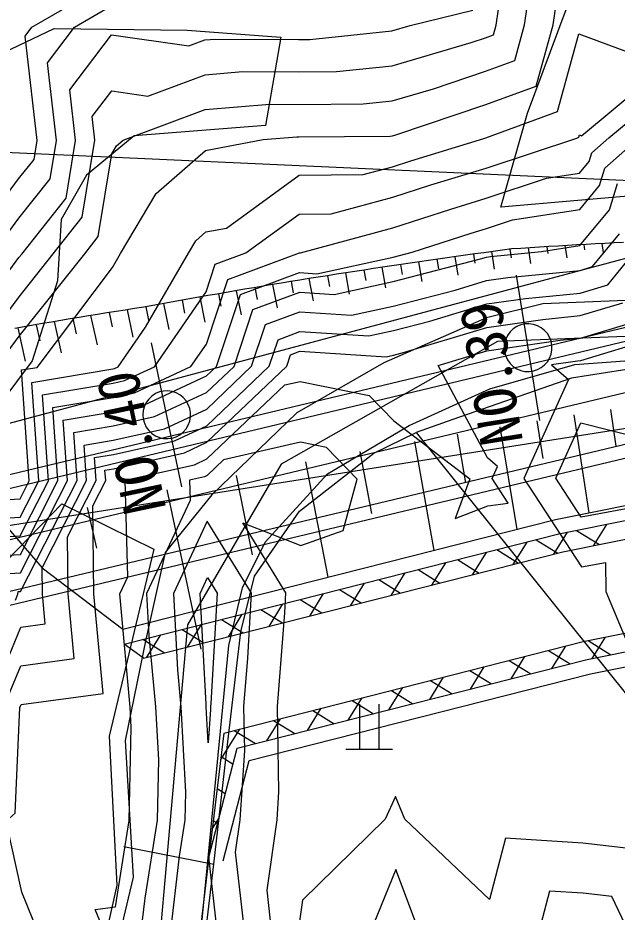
# Model space of a CAD drawing. Extents: x 42655 to 43811, y -141820 to -141156.
# Drawn here: x 43280.88 to 43313.48, y -141374.58 to -141325.97 of the extents above; entities that cross this region are included whole.
import ezdxf

# ---------------------------------------------------------------- set-up
doc = ezdxf.new("R2010")
doc.units = 0
for name, color, linetype in [('D-BMK-HTXT_1', 7, 'Continuous'), ('D-BMK_1', 7, 'Continuous'), ('D-STR', 7, 'Continuous'), ('D-STR-STR4_1', 7, 'Continuous'), ('D-STR-STR5_1', 7, 'Continuous'), ('D-STR_1', 7, 'Continuous'), ('ZE_HICN', 7, 'Continuous'), ('ZE_LWCN', 7, 'Continuous'), ('地形', 7, 'Continuous'), ('現況水路ﾊｯﾁ', 7, 'Continuous')]:
    doc.layers.add(name, color=color, linetype=linetype)

msp = doc.modelspace()

# ---------------------------------------------------------------- linework, layer by layer
at = {"layer": 'D-BMK-HTXT_1'}
for p, q in [((43439.808, -141340.537), (43274.802, -141333.044)), ((43309.27, -141347.849), (43308.009, -141339.949)), ((43289.804, -141351.457), (43288.149, -141343.63))]:
    msp.add_line(p, q, dxfattribs=at)
for points in [[(43307.339, -141343.899), (43307.36, -141344.131), (43307.422, -141344.356), (43307.524, -141344.566), (43307.66, -141344.754), (43307.829, -141344.915), (43308.023, -141345.044), (43308.238, -141345.135), (43308.465, -141345.187), (43308.698, -141345.198), (43308.929, -141345.166), (43309.15, -141345.094), (43309.356, -141344.984), (43309.538, -141344.839), (43309.691, -141344.663), (43309.811, -141344.463), (43309.893, -141344.245), (43309.934, -141344.015), (43309.934, -141343.782), (43309.893, -141343.553), (43309.811, -141343.335), (43309.691, -141343.135), (43309.538, -141342.959), (43309.356, -141342.814), (43309.15, -141342.703), (43308.929, -141342.631), (43308.698, -141342.6), (43308.465, -141342.611), (43308.238, -141342.663), (43308.023, -141342.754), (43307.829, -141342.883), (43307.66, -141343.044), (43307.523, -141343.232), (43307.422, -141343.442), (43307.36, -141343.667), (43307.339, -141343.899)], [(43287.677, -141347.544), (43287.697, -141347.776), (43287.759, -141348.001), (43287.861, -141348.211), (43287.998, -141348.399), (43288.166, -141348.56), (43288.361, -141348.689), (43288.575, -141348.78), (43288.802, -141348.832), (43289.035, -141348.843), (43289.266, -141348.811), (43289.487, -141348.739), (43289.693, -141348.629), (43289.875, -141348.483), (43290.028, -141348.308), (43290.148, -141348.108), (43290.23, -141347.89), (43290.271, -141347.66), (43290.271, -141347.427), (43290.23, -141347.198), (43290.148, -141346.98), (43290.028, -141346.78), (43289.875, -141346.604), (43289.693, -141346.459), (43289.487, -141346.348), (43289.266, -141346.276), (43289.035, -141346.245), (43288.802, -141346.256), (43288.575, -141346.307), (43288.361, -141346.399), (43288.166, -141346.527), (43287.998, -141346.689), (43287.861, -141346.877), (43287.759, -141347.087), (43287.697, -141347.312), (43287.677, -141347.544)]]:
    msp.add_lwpolyline(points, dxfattribs=at)
at = {"layer": 'D-BMK_1'}
msp.add_lwpolyline([(43339.878, -141340.165), (43219.961, -141368.793)], dxfattribs=at)
at = {"layer": 'D-STR'}
for p, q in [((43312.899, -141353.503), (43312.177, -141354.668)), ((43310.766, -141353.932), (43310.026, -141355.127)), ((43311.272, -141353.83), (43312.516, -141354.6)), ((43308.569, -141354.464), (43307.812, -141355.687)), ((43309.074, -141354.336), (43310.257, -141355.068)), ((43306.355, -141355.024), (43305.597, -141356.247)), ((43306.934, -141354.878), (43308.116, -141355.61)), ((43304.794, -141355.419), (43305.976, -141356.152)), ((43302.653, -141355.961), (43303.835, -141356.693)), ((43304.14, -141355.585), (43303.383, -141356.808)), ((43300.513, -141356.502), (43301.695, -141357.235)), ((43301.926, -141356.145), (43301.168, -141357.368)), ((43299.712, -141356.705), (43298.954, -141357.928)), ((43297.497, -141357.265), (43296.74, -141358.489)), ((43298.372, -141357.044), (43299.554, -141357.776)), ((43295.283, -141357.826), (43294.525, -141359.049)), ((43296.232, -141357.586), (43297.414, -141358.318)), ((43293.069, -141358.386), (43292.311, -141359.609)), ((43294.091, -141358.127), (43295.274, -141358.86)), ((43291.951, -141358.669), (43293.133, -141359.401)), ((43289.81, -141359.21), (43290.993, -141359.943)), ((43290.854, -141358.946), (43290.097, -141360.169)), ((43287.67, -141359.752), (43288.852, -141360.484)), ((43288.64, -141359.507), (43287.882, -141360.73)), ((43311.904, -141359.823), (43313.147, -141360.593)), ((43312.835, -141359.636), (43312.113, -141360.801)), ((43287.716, -141360.772), (43286.667, -141360.006)), ((43309.75, -141360.356), (43310.93, -141361.087)), ((43310.666, -141360.124), (43309.909, -141361.346)), ((43308.45, -141360.687), (43307.695, -141361.906)), ((43306.234, -141361.25), (43305.48, -141362.466)), ((43307.612, -141360.9), (43308.789, -141361.629)), ((43304.017, -141361.813), (43303.266, -141363.026)), ((43305.474, -141361.443), (43306.649, -141362.17)), ((43303.336, -141361.986), (43304.508, -141362.712)), ((43301.801, -141362.376), (43301.051, -141363.587)), ((43301.198, -141362.529), (43302.368, -141363.254)), ((43299.585, -141362.939), (43298.837, -141364.147)), ((43299.061, -141363.072), (43300.227, -141363.795)), ((43297.369, -141363.502), (43296.623, -141364.707)), ((43296.923, -141363.616), (43298.087, -141364.337)), ((43295.153, -141364.065), (43294.408, -141365.268)), ((43294.785, -141364.159), (43295.946, -141364.878)), ((43292.937, -141364.629), (43291.911, -141366.284)), ((43292.647, -141364.702), (43293.806, -141365.42)), ((43292.087, -141364.845), (43291.266, -141371.584)), ((43291.266, -141371.584), (43292.808, -141365.672)), ((43291.931, -141366.126), (43292.584, -141366.531)), ((43292.04, -141371.786), (43293.463, -141366.332)), ((43291.719, -141367.862), (43292.165, -141368.138)), ((43291.826, -141369.436), (43291.454, -141370.037)), ((43291.508, -141369.599), (43291.746, -141369.746)), ((43286.641, -141371.017), (43291.547, -141371.981)), ((43291.296, -141371.335), (43291.326, -141371.353))]:
    msp.add_line(p, q, dxfattribs=at)
for points in [[(43286.592, -141359.199), (43310.131, -141353.244), (43329.384, -141349.374), (43339.497, -141347.728), (43344.858, -141358.537)], [(43286.667, -141360.006), (43310.308, -141354.024), (43329.528, -141350.161), (43339.043, -141348.612), (43344.134, -141358.878)], [(43287.716, -141360.772), (43310.53, -141355), (43329.706, -141351.145), (43338.475, -141349.718), (43343.23, -141359.304)], [(43292.087, -141364.845), (43311.636, -141359.877), (43330.601, -141356.065), (43335.636, -141355.246), (43338.236, -141361.658)], [(43292.808, -141365.672), (43311.857, -141360.853), (43330.78, -141357.049), (43335.009, -141356.361), (43337.332, -141362.083)], [(43293.463, -141366.332), (43312.034, -141361.633), (43330.923, -141357.836), (43334.508, -141357.253), (43336.61, -141362.424)]]:
    msp.add_lwpolyline(points, dxfattribs=at)
at = {"layer": 'D-STR-STR4_1'}
for p, q in [((43313.118, -141347.254), (43313.418, -141349.26)), ((43311.123, -141347.558), (43311.947, -141352.879)), ((43307.099, -141348.202), (43308.02, -141353.778)), ((43309.11, -141347.874), (43309.437, -141349.918)), ((43304.777, -141348.593), (43305.23, -141351.238)), ((43302.457, -141348.997), (43303.511, -141354.931)), ((43299.492, -141349.536), (43300.119, -141352.912)), ((43296.532, -141350.096), (43297.746, -141356.377)), ((43292.75, -141350.846), (43293.626, -141355.153)), ((43288.975, -141351.633), (43290.825, -141360.293)), ((43284.651, -141352.582), (43285.148, -141354.789)), ((43280.239, -141353.603), (43282.194, -141355.865)), ((43282.194, -141355.865), (43286.592, -141359.199))]:
    msp.add_line(p, q, dxfattribs=at)
at = {"layer": 'D-STR-STR5_1'}
for p, q in [((43308.788, -141339.32), (43308.655, -141338.475)), ((43309.659, -141338.413), (43309.718, -141338.789)), ((43310.764, -141339.014), (43310.664, -141338.353)), ((43311.668, -141338.295), (43311.71, -141338.58)), ((43312.742, -141338.717), (43312.672, -141338.24)), ((43304.84, -141339.961), (43304.671, -141338.953)), ((43305.664, -141338.815), (43305.745, -141339.306)), ((43306.813, -141339.635), (43306.658, -141338.679)), ((43307.651, -141338.546), (43307.726, -141339.011)), ((43301.692, -141339.381), (43301.788, -141339.924)), ((43302.868, -141340.296), (43302.685, -141339.236)), ((43303.678, -141339.093), (43303.766, -141339.61)), ((43298.93, -141340.996), (43298.717, -141339.832)), ((43299.708, -141339.68), (43299.811, -141340.248)), ((43300.898, -141340.641), (43300.7, -141339.529)), ((43295.744, -141340.305), (43295.862, -141340.926)), ((43296.963, -141341.36), (43296.735, -141340.145)), ((43297.726, -141339.988), (43297.836, -141340.582)), ((43293.036, -141342.118), (43292.774, -141340.801)), ((43293.764, -141340.633), (43293.89, -141341.279)), ((43294.998, -141341.735), (43294.754, -141340.468)), ((43289.808, -141341.318), (43289.951, -141342.015)), ((43291.075, -141342.512), (43290.796, -141341.143)), ((43291.785, -141340.971), (43291.92, -141341.642)), ((43287.159, -141343.329), (43286.839, -141341.834)), ((43287.832, -141341.675), (43287.984, -141342.398)), ((43289.116, -141342.916), (43288.82, -141341.495)), ((43283.862, -141342.316), (43284.045, -141343.141)), ((43285.204, -141343.751), (43284.854, -141342.153)), ((43285.847, -141341.992), (43286.014, -141342.765)), ((43281.301, -141344.626), (43280.887, -141342.82)), ((43281.878, -141342.65), (43282.077, -141343.527)), ((43283.251, -141344.184), (43282.87, -141342.481))]:
    msp.add_line(p, q, dxfattribs=at)
msp.add_lwpolyline([(43313.829, -141338.18), (43313.322, -141338.206), (43312.815, -141338.232), (43312.308, -141338.26), (43311.8, -141338.288), (43311.293, -141338.316), (43310.786, -141338.345), (43310.279, -141338.375), (43309.772, -141338.406), (43309.265, -141338.437), (43308.758, -141338.469), (43308.25, -141338.501), (43307.743, -141338.534), (43307.241, -141338.601), (43306.739, -141338.668), (43306.237, -141338.736), (43305.736, -141338.805), (43305.234, -141338.874), (43304.732, -141338.944), (43304.231, -141339.015), (43303.729, -141339.086), (43303.228, -141339.158), (43302.727, -141339.23), (43302.225, -141339.303), (43301.724, -141339.377), (43301.223, -141339.451), (43300.722, -141339.526), (43300.221, -141339.602), (43299.72, -141339.678), (43299.22, -141339.755), (43298.719, -141339.832), (43298.218, -141339.91), (43297.718, -141339.989), (43297.217, -141340.068), (43296.717, -141340.148), (43296.217, -141340.229), (43295.717, -141340.31), (43295.216, -141340.392), (43294.716, -141340.474), (43294.216, -141340.557), (43293.717, -141340.641), (43293.217, -141340.725), (43292.717, -141340.81), (43292.218, -141340.896), (43291.718, -141340.982), (43291.219, -141341.069), (43290.719, -141341.157), (43290.22, -141341.245), (43289.721, -141341.333), (43289.222, -141341.423), (43288.723, -141341.513), (43288.224, -141341.603), (43287.725, -141341.695), (43287.224, -141341.773), (43286.722, -141341.852), (43286.221, -141341.932), (43285.72, -141342.012), (43285.219, -141342.093), (43284.717, -141342.175), (43284.216, -141342.257), (43283.715, -141342.34), (43283.214, -141342.424), (43282.713, -141342.508), (43282.213, -141342.593), (43281.712, -141342.678), (43281.211, -141342.764), (43280.711, -141342.851)], dxfattribs=at)
at = {"layer": 'D-STR_1'}
for points in [[(43339.6, -141336.676), (43218.633, -141365.555)], [(43339.659, -141337.424), (43218.917, -141366.249)], [(43317.868, -141337.995), (43218.254, -141364.63)], [(43340.097, -141342.907), (43221.004, -141371.338)], [(43340.157, -141343.654), (43221.288, -141372.032)], [(43340.196, -141344.153), (43280.239, -141353.603)]]:
    msp.add_lwpolyline(points, dxfattribs=at)
at = {"layer": 'ZE_HICN'}
for points in [[(43278.608, -141342.146), (43280.936, -141339.002), (43281.089, -141338.809), (43283.504, -141335.764), (43284.022, -141332.633), (43283.709, -141329.882), (43285.967, -141326.888), (43290.184, -141327.5), (43291.057, -141327.174), (43291.628, -141327.127), (43296.145, -141327.152), (43296.754, -141327.147), (43301.231, -141326.674), (43302.22, -141326.384), (43305.636, -141325.548)], [(43278.496, -141354.267), (43281.007, -141354.126), (43282.537, -141351.128), (43282.212, -141346.47), (43286.057, -141345.831), (43286.672, -141345.692), (43288.309, -141344.938), (43291.121, -141340.864), (43291.617, -141339.368), (43293.288, -141338.752), (43296.189, -141336.641), (43297.926, -141336.626), (43301.273, -141335.724), (43303.347, -141335.057), (43306.354, -141334.138), (43311.283, -141332.504), (43311.4, -141332.462), (43311.434, -141332.338), (43311.538, -141332.377), (43316.503, -141328.263)], [(43280.102, -141363.465), (43281.041, -141361.189), (43283.944, -141360.803), (43283.615, -141357.285), (43283.573, -141354.179), (43285.136, -141351.116), (43285.049, -141349.872), (43286.075, -141349.702), (43289.391, -141348.954), (43291.156, -141348.141), (43294.555, -141344.908), (43295.033, -141343.466), (43296.22, -141343.028), (43299.971, -141343.263), (43301.307, -141342.973), (43303.293, -141342.459), (43306.389, -141341.524), (43308.489, -141341.225), (43311.474, -141340.929), (43312.972, -141340.476), (43314.164, -141339.028)], [(43291.237, -141365.373), (43291.131, -141363.413), (43291.119, -141363.282), (43290.791, -141357.252), (43291.194, -141356.391), (43291.722, -141357.247), (43291.369, -141363.24), (43291.355, -141363.412), (43291.358, -141363.568), (43291.237, -141365.373)], [(43291.288, -141376.285), (43291.744, -141375.735), (43291.266, -141371.584), (43290.785, -141375.74), (43291.288, -141376.285)]]:
    msp.add_lwpolyline(points, dxfattribs=at)
at = {"layer": 'ZE_LWCN'}
for points in [[(43276.892, -141352.342), (43280.998, -141352.112), (43281.497, -141351.133), (43281.078, -141345.109), (43281.924, -141344.968), (43286.027, -141339.541), (43286.466, -141338.784), (43288.402, -141335.512), (43291.085, -141333.176), (43294.232, -141332.585), (43296.052, -141332.434), (43296.17, -141332.435), (43301.127, -141332.394), (43301.258, -141332.38), (43301.443, -141332.326), (43306.338, -141330.679), (43309.079, -141329.678), (43309.998, -141326.348), (43310.793, -141320.891)], [(43280.291, -141344.165), (43280.956, -141343.267), (43284.516, -141338.793), (43285.254, -141337.863), (43285.998, -141333.363), (43286.252, -141332.933), (43286.611, -141332.621), (43291.075, -141330.955), (43294.578, -141330.665), (43296.161, -141330.674), (43299.669, -141330.645), (43301.249, -141330.478), (43303.491, -141329.821), (43306.329, -141328.866), (43307.919, -141328.286), (43308.451, -141326.355), (43308.913, -141323.191)], [(43277.889, -141338.824), (43280.916, -141334.723), (43281.755, -141333.665), (43281.924, -141332.643), (43281.278, -141326.966), (43281.644, -141326.481), (43285.954, -141323.985)], [(43279.484, -141338.817), (43280.926, -141336.863), (43282.629, -141334.715), (43282.973, -141332.638), (43282.494, -141328.424), (43283.967, -141326.47), (43285.96, -141325.316)], [(43279.449, -141343.155), (43280.946, -141341.134), (43282.803, -141338.801), (43284.379, -141336.813), (43285.071, -141332.628), (43284.925, -141331.34), (43285.982, -141329.939), (43287.955, -141330.225), (43291.066, -141329.065), (43293.103, -141328.896), (43296.153, -141328.913), (43298.211, -141328.896), (43301.24, -141328.576), (43305.539, -141327.317), (43306.321, -141327.054), (43306.758, -141326.894), (43306.905, -141326.362), (43307.032, -141325.491)], [(43277.694, -141353.305), (43281.003, -141353.119), (43282.017, -141351.13), (43281.645, -141345.789), (43286.053, -141345.057), (43286.128, -141345.04), (43286.33, -141344.947), (43287.823, -141342.783), (43290.153, -141338.767), (43290.552, -141338.091), (43291.106, -141337.609), (43292.226, -141337.399), (43296.18, -141334.524), (43299.671, -141334.493), (43301.265, -141334.063), (43302.253, -141333.745), (43306.237, -141332.528), (43306.346, -141332.491), (43310.239, -141331.07), (43311.408, -141326.836), (43314.979, -141328.169)], [(43279.298, -141355.229), (43281.012, -141355.133), (43283.057, -141351.125), (43282.78, -141347.15), (43286.06, -141346.605), (43287.216, -141346.345), (43290.289, -141344.929), (43291.135, -141343.703), (43292.3, -141340.188), (43296.199, -141338.749), (43296.209, -141338.749), (43296.262, -141338.738), (43301.281, -141337.385), (43304.44, -141336.368), (43306.362, -141335.781), (43309.643, -141334.694), (43311.443, -141334.413), (43311.967, -141333.777), (43312.11, -141333.314), (43313.032, -141332.496), (43316.509, -141329.614)], [(43280.1, -141356.191), (43281.017, -141356.14), (43283.576, -141351.123), (43283.347, -141347.831), (43286.064, -141347.379), (43287.76, -141346.997), (43291.143, -141345.438), (43291.686, -141344.922), (43292.983, -141341.008), (43296.204, -141339.819), (43297.149, -141339.878), (43301.289, -141338.98), (43302.336, -141338.709), (43305.534, -141337.68), (43306.369, -141337.425), (43307.797, -141336.952), (43311.453, -141336.382), (43312.516, -141335.09), (43312.806, -141334.149), (43314.678, -141332.488)], [(43280.757, -141357.622), (43280.882, -141357.298), (43280.902, -141357.153), (43281.022, -141357.147), (43284.096, -141351.12), (43283.914, -141348.511), (43286.067, -141348.154), (43288.304, -141347.649), (43291.147, -141346.339), (43292.642, -141344.917), (43293.666, -141341.827), (43296.21, -141340.888), (43298.09, -141341.006), (43301.295, -141340.311), (43306.058, -141339.079), (43306.377, -141338.982), (43306.593, -141338.952), (43309.376, -141338.676), (43311.462, -141338.351), (43313.066, -141336.403), (43313.502, -141334.984)], [(43279.224, -141363.469), (43281.031, -141359.085), (43282.365, -141358.908), (43282.214, -141357.292), (43282.194, -141355.865), (43284.616, -141351.118), (43284.482, -141349.192), (43286.071, -141348.928), (43288.847, -141348.302), (43291.151, -141347.24), (43293.598, -141344.913), (43294.35, -141342.647), (43296.215, -141341.958), (43299.031, -141342.135), (43301.301, -141341.642), (43304.675, -141340.769), (43306.383, -141340.253), (43307.541, -141340.088), (43311.468, -141339.699), (43312.152, -141339.492), (43313.615, -141337.715)], [(43282.012, -141375.781), (43281.099, -141373.486), (43280.246, -141369.627), (43280.73, -141369.202), (43280.981, -141363.46), (43281.051, -141363.292), (43285.524, -141362.697), (43285.017, -141357.279), (43284.951, -141352.493), (43285.655, -141351.113), (43285.616, -141350.553), (43286.078, -141350.476), (43289.935, -141349.606), (43291.16, -141349.042), (43295.511, -141344.904), (43295.716, -141344.286), (43296.225, -141344.098), (43300.912, -141344.391), (43301.314, -141344.304), (43301.911, -141344.15), (43306.395, -141342.794), (43309.436, -141342.362), (43311.48, -141342.159), (43313.792, -141341.46)], [(43285.62, -141375.764), (43285.091, -141374.434), (43286.191, -141374.29), (43286.941, -141369.595), (43287.042, -141364.518), (43286.983, -141363.432), (43286.453, -141357.684), (43286.43, -141357.272), (43286.857, -141356.36), (43286.713, -141351.108), (43290.479, -141350.259), (43291.164, -141349.943), (43295.396, -141345.918), (43296.232, -141345.729), (43299.994, -141346.494), (43301.331, -141347.879), (43305.471, -141351.02), (43304.663, -141353.18), (43306.441, -141352.503), (43307.553, -141352.358), (43306.677, -141351.014), (43306.974, -141350.354), (43306.428, -141349.88), (43303.754, -141344.865), (43306.401, -141344.065), (43310.384, -141343.499), (43311.486, -141343.389), (43314.612, -141342.444)], [(43315.432, -141343.427), (43311.492, -141344.619), (43311.331, -141344.635), (43309.92, -141344.836), (43310.836, -141345.631), (43308.413, -141351.006), (43311.544, -141355.808), (43312.848, -141355.567), (43312.876, -141357.147), (43314.216, -141360.351)], [(43315.442, -141352.395), (43311.532, -141353.117), (43310.15, -141350.998), (43311.507, -141347.986), (43314.811, -141348.809)], [(43294.702, -141375.721), (43294.433, -141373.386), (43294.977, -141369.557), (43295.079, -141368.033), (43295.003, -141363.394), (43295.4, -141358.31), (43295.463, -141357.23), (43293.115, -141353.421), (43296.274, -141354.643), (43298.57, -141353.837), (43299.33, -141351.049), (43297.673, -141349.332), (43296.248, -141349.042), (43292.068, -141349.988), (43291.168, -141350.844), (43291.023, -141350.911), (43290.222, -141351.092), (43290.253, -141352.208), (43287.884, -141357.265), (43288.008, -141359.55), (43288.366, -141363.426), (43288.521, -141366.293), (43288.455, -141369.588), (43287.777, -141373.829), (43287.554, -141375.755)], [(43291.297, -141378.05), (43293.223, -141375.728), (43292.716, -141371.326), (43292.966, -141369.567), (43293.219, -141365.801), (43293.179, -141363.403), (43293.384, -141360.775), (43293.593, -141357.238), (43291.18, -141353.325), (43289.338, -141357.258), (43289.563, -141361.416), (43289.748, -141363.419), (43289.999, -141368.067), (43289.969, -141369.581), (43289.658, -141371.53), (43289.17, -141375.747), (43291.297, -141378.05)], [(43315.234, -141371.244), (43311.615, -141370.836), (43307.405, -141370.564), (43306.541, -141373.888), (43301.929, -141369.524), (43301.427, -141368.294), (43300.867, -141369.529), (43296.365, -141373.933), (43296.15, -141375.445)], [(43301.463, -141375.874), (43302.734, -141375.683), (43301.446, -141372.266), (43300.048, -141375.696), (43301.463, -141375.874)], [(43314.102, -141375.63), (43313.202, -141373.728), (43311.628, -141373.551), (43309.797, -141373.433), (43309.219, -141375.653)]]:
    msp.add_lwpolyline(points, dxfattribs=at)
at = {"layer": '地形'}
for p, q in [((43299.46, -141363.281), (43299.46, -141365.723)), ((43300.524, -141363.281), (43300.524, -141365.723)), ((43298.722, -141365.723), (43301.267, -141365.723))]:
    msp.add_line(p, q, dxfattribs=at)
for points in [[(43312.095, -141314.847), (43325.006, -141315.563), (43325.993, -141319.415), (43326.62, -141324.343), (43326.172, -141329.628), (43323.393, -141333.749), (43319.716, -141335.183), (43307.163, -141336.258), (43308.598, -141331.152), (43311.108, -141324.433), (43312.184, -141319.057), (43312.095, -141314.847)], [(43294.351, -141331.831), (43287.212, -141332.387), (43284.616, -141334.517), (43283.225, -141336.926), (43283.04, -141340.261), (43281.649, -141344.615), (43277.477, -141350.173), (43268.484, -141357.862), (43265.795, -141360.456), (43262.364, -141362.216), (43259.675, -141361.29), (43259.954, -141358.047), (43259.49, -141353.323), (43267.278, -141348.135), (43273.583, -141344.43), (43277.292, -141341.558), (43278.126, -141337.667), (43277.57, -141330.534), (43278.96, -141328.403), (43282.854, -141326.551), (43290.086, -141326.643), (43295.186, -141327.014), (43294.351, -141331.831)], [(43320.416, -141343.042), (43306.981, -141343.562), (43295.205, -141350.231), (43290.102, -141358.972), (43288.329, -141378.975), (43281.035, -141399.699), (43275.615, -141412.936), (43269.57, -141418.666), (43258.406, -141420.545), (43248.616, -141416.071), (43236.326, -141403.584), (43228.932, -141399.526), (43212.545, -141401.296), (43179.843, -141406.5), (43173.386, -141405.147), (43168.699, -141401.089), (43165.679, -141389.851), (43160.467, -141365.786), (43157.022, -141355.032), (43149.624, -141339.614), (43144.729, -141329.729)], [(43315.311, -141341.272), (43309.433, -141341.519), (43306.376, -141342.285), (43300.782, -141344.731), (43296.062, -141347.439), (43291.429, -141351.893), (43288.894, -141355.038), (43287.845, -141359.755), (43286.709, -141365.257), (43287.146, -141372.682), (43286.01, -141377.486), (43284.612, -141383.862), (43280.577, -141394.623), (43277.936, -141401.441), (43275.185, -141409.688), (43270.894, -141415.406), (43265.171, -141418.155), (43260.44, -141418.375), (43254.607, -141417.496), (43248.225, -141413.647), (43241.182, -141405.95)], [(43254.565, -141421.843), (43254.731, -141421.919), (43258.042, -141422.448), (43262.082, -141422.25), (43266.784, -141421.522), (43271.221, -141420.264), (43273.538, -141418.478), (43275.724, -141415.632), (43277.843, -141412.588), (43279.498, -141408.353), (43289.54, -141382.032), (43290.204, -141379.986), (43290.671, -141378), (43290.847, -141375.546), (43292.348, -141360.087), (43293.092, -141356.951), (43294.33, -141354.475), (43297.716, -141350.762), (43302.176, -141348.121), (43306.553, -141346.14), (43311.178, -141344.82), (43316.628, -141344.407)], [(43327.481, -141362.474), (43328.868, -141357.564), (43327.827, -141352.769), (43325.052, -141348.379), (43323.202, -141346.126), (43321.302, -141345.158), (43317.152, -141344.798), (43315.619, -141344.838), (43311, -141345.554), (43304.545, -141347.803), (43302.54, -141348.516)], [(43320.732, -141373.109), (43318.852, -141375.743), (43317.115, -141376.953), (43305.989, -141377.254), (43290.827, -141377.917), (43291.547, -141371.981), (43292.268, -141365.638), (43293.014, -141359.344), (43293.76, -141356.314), (43296.197, -141352.782), (43300.249, -141349.627), (43302.54, -141348.516)], [(43302.54, -141348.516), (43317.101, -141366.616), (43317.369, -141369.542), (43320.732, -141373.109)], [(43288.267, -141354.855), (43285.848, -141365.022), (43286.267, -141373.121), (43283.514, -141385.454), (43279.342, -141386.896), (43276.006, -141392.479), (43271.085, -141402.146), (43263.495, -141406.646), (43258.074, -141408.063), (43249.233, -141407.397), (43252.319, -141404.646), (43256.322, -141401.063), (43260.326, -141396.896), (43262.077, -141391.23), (43264.079, -141381.71), (43266.164, -141374.043), (43268.332, -141368.119), (43272.002, -141363.119), (43277.924, -141357.869), (43283.274, -141352.393), (43288.267, -141354.855)]]:
    msp.add_lwpolyline(points, dxfattribs=at)
at = {"layer": '現況水路ﾊｯﾁ'}
for points in [[(43315.311, -141341.272), (43309.433, -141341.519), (43306.376, -141342.285), (43300.782, -141344.731), (43296.062, -141347.439), (43291.429, -141351.893), (43288.894, -141355.038), (43287.845, -141359.755), (43286.709, -141365.257), (43287.146, -141372.682), (43286.01, -141377.486), (43284.612, -141383.862), (43280.577, -141394.623), (43277.936, -141401.441), (43275.185, -141409.688), (43270.894, -141415.406), (43265.171, -141418.155), (43260.44, -141418.375), (43254.607, -141417.496), (43248.225, -141413.647), (43241.182, -141405.95)], [(43279.498, -141408.353), (43289.54, -141382.032), (43290.204, -141379.986), (43290.671, -141378), (43290.847, -141375.546), (43292.348, -141360.087), (43293.092, -141356.951), (43294.33, -141354.475), (43297.716, -141350.762), (43302.176, -141348.121), (43306.553, -141346.14), (43311.178, -141344.82), (43316.628, -141344.407)]]:
    msp.add_lwpolyline(points, dxfattribs=at)

# ---------------------------------------------------------------- texts
at = {"layer": 'D-BMK-HTXT_1'}
for s, rotation, p in [('NO.39', 99.0687, (43308.366, -141349.006)), ('NO.40', 101.9335, (43288.959, -141352.658))]:
    msp.add_text(s, height=2.3065, rotation=rotation, dxfattribs=at).set_placement(p)

doc.saveas('drawing.dxf')
